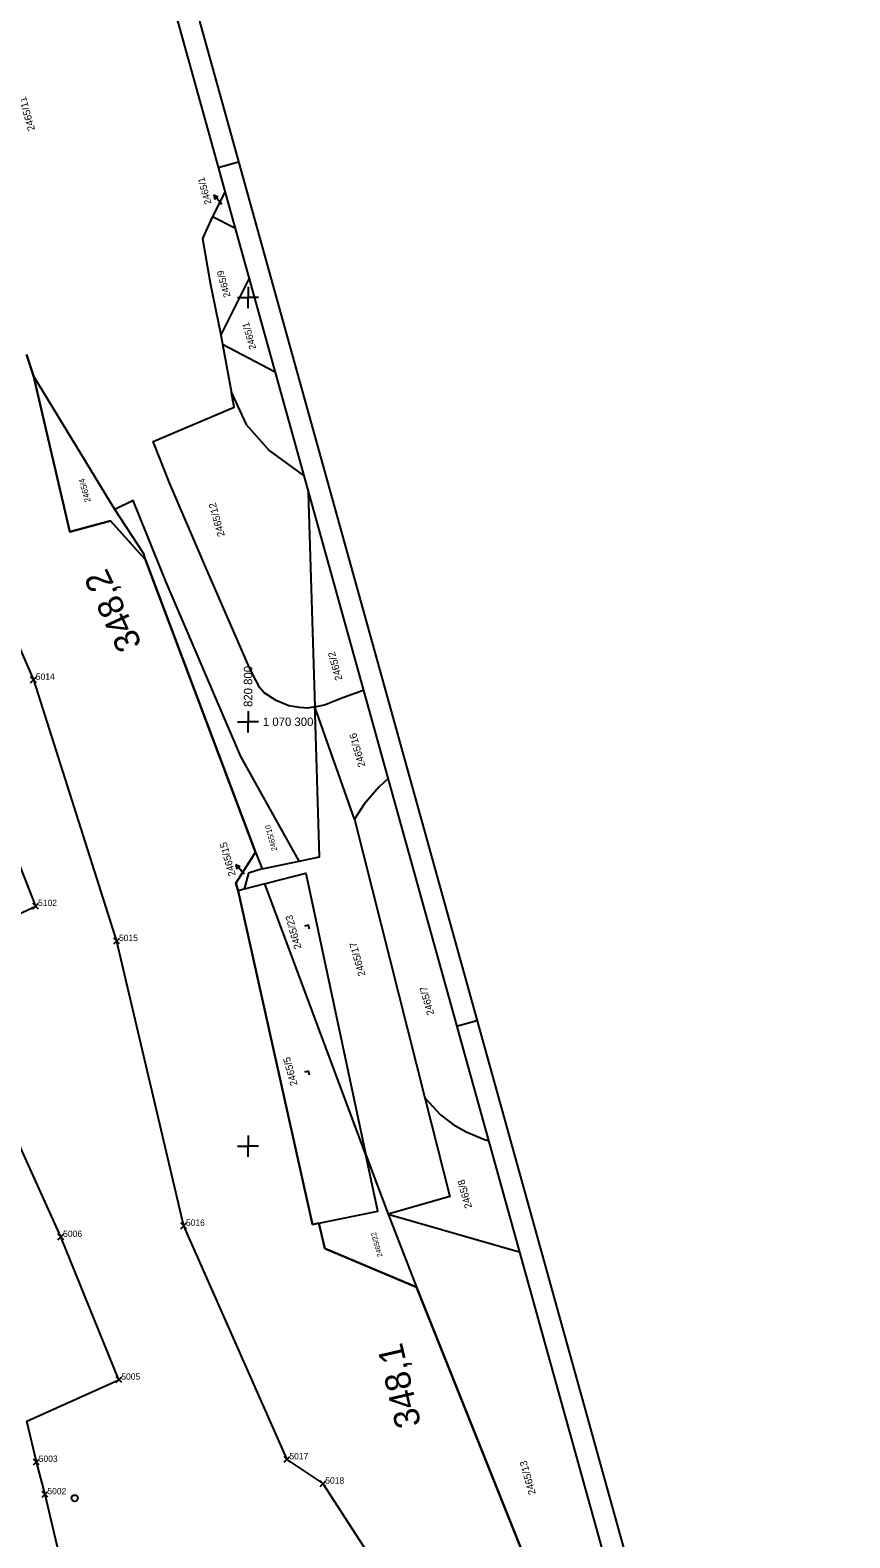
# Model space of a CAD drawing. Extents: x -821172 to -820632, y -1070921 to -1069931.
# Drawn here: x -820825.7 to -820729.1, y -1070396.2 to -1070218.5 of the extents above; entities that cross this region are included whole.
import ezdxf

# ---------------------------------------------------------------- set-up
doc = ezdxf.new("R2010")
doc.units = 0
for name, color, linetype in [('Ram', 7, 'Continuous'), ('Sit', 7, 'Continuous'), ('Sttaniceni a namezniky', 7, 'Continuous'), ('VB_bod_DZ', 7, 'Continuous'), ('Vrstva 52', 7, 'Continuous'), ('Vrstva 53', 7, 'Continuous'), ('Vrstva 55', 7, 'Continuous'), ('Vrstva 57', 7, 'Continuous'), ('Vrstva 59', 7, 'Continuous')]:
    doc.layers.add(name, color=color, linetype=linetype)

msp = doc.modelspace()

# ---------------------------------------------------------------- linework, layer by layer
at = {"layer": 'Ram'}
for p, q in [((-820801.13, -1070234.05), (-820803.54, -1070234.72)), ((-820773.02, -1070335.22), (-820775.42, -1070335.89))]:
    msp.add_line(p, q, dxfattribs=at)
for points in [[(-820857.35, -1070031.72), (-820632.46, -1070841.06)], [(-820859.09, -1070034.8), (-820635.54, -1070839.32), (-820916.88, -1070917.49)]]:
    msp.add_lwpolyline(points, dxfattribs=at)
at = {"layer": 'Sit'}
for p, q in [((-820800, -1070248.75), (-820800, -1070250)), ((-820800, -1070248.75), (-820800, -1070250)), ((-820801.25, -1070250), (-820800, -1070250)), ((-820801.25, -1070250), (-820800, -1070250)), ((-820798.75, -1070250), (-820800, -1070250)), ((-820800, -1070251.25), (-820800, -1070250)), ((-820800, -1070251.25), (-820800, -1070250)), ((-820798.75, -1070250), (-820800, -1070250)), ((-820801.25, -1070300), (-820800, -1070300)), ((-820800, -1070298.75), (-820800, -1070300)), ((-820798.75, -1070300), (-820800, -1070300)), ((-820800, -1070301.25), (-820800, -1070300)), ((-820801.25, -1070350), (-820800, -1070350)), ((-820800, -1070348.75), (-820800, -1070350)), ((-820798.75, -1070350), (-820800, -1070350)), ((-820800, -1070351.25), (-820800, -1070350))]:
    msp.add_line(p, q, dxfattribs=at)
at = {"layer": 'Sttaniceni a namezniky'}
msp.add_circle((-820820.44, -1070391.49), 0.375, dxfattribs=at)
at = {"layer": 'VB_bod_DZ'}
for p, q in [((-820825.63, -1070295.4), (-820824.95, -1070294.71)), ((-820824.95, -1070295.4), (-820825.63, -1070294.71)), ((-820825.37, -1070322.06), (-820824.69, -1070321.37)), ((-820824.69, -1070322.06), (-820825.37, -1070321.37)), ((-820815.83, -1070326.18), (-820815.15, -1070325.49)), ((-820815.15, -1070326.18), (-820815.83, -1070325.49)), ((-820822.41, -1070361.04), (-820821.72, -1070360.35)), ((-820821.72, -1070361.04), (-820822.41, -1070360.35)), ((-820807.94, -1070359.74), (-820807.25, -1070359.05)), ((-820807.25, -1070359.74), (-820807.94, -1070359.05)), ((-820815.56, -1070377.87), (-820814.87, -1070377.18)), ((-820814.87, -1070377.87), (-820815.56, -1070377.18)), ((-820825.29, -1070387.56), (-820824.6, -1070386.87)), ((-820824.6, -1070387.56), (-820825.29, -1070386.87)), ((-820795.76, -1070387.25), (-820795.07, -1070386.56)), ((-820795.07, -1070387.25), (-820795.76, -1070386.56)), ((-820824.27, -1070391.37), (-820823.58, -1070390.69)), ((-820823.58, -1070391.37), (-820824.27, -1070390.69)), ((-820791.52, -1070390.12), (-820790.83, -1070389.43)), ((-820790.83, -1070390.12), (-820791.52, -1070389.43))]:
    msp.add_line(p, q, dxfattribs=at)
at = {"layer": 'Vrstva 52'}
msp.add_lwpolyline([(-820782.06, -1070569.19), (-820823.93, -1070391.03), (-820824.95, -1070387.21), (-820826.08, -1070382.39), (-820815.22, -1070377.53), (-820822.07, -1070360.7), (-820836.66, -1070328.48), (-820839.3, -1070322.5), (-820846.11, -1070309.46), (-820851.46, -1070300.37), (-820856.81, -1070291.29), (-820843.48, -1070284.13), (-820833.99, -1070279.04), (-820832.86, -1070278.43), (-820830.46, -1070283.22), (-820825.29, -1070295.05), (-820815.49, -1070325.84), (-820807.6, -1070359.39), (-820795.41, -1070386.91), (-820791.18, -1070389.77), (-820780.82, -1070405.78)], dxfattribs=at)
msp.add_lwpolyline([(-820839.58, -1070284.56), (-820853.94, -1070291.42), (-820836.24, -1070326.89), (-820825.03, -1070321.71)], close=True, dxfattribs=at)
at = {"layer": 'Vrstva 53'}
for p, q in [((-820826.1, -1070256.7), (-820825.3, -1070259.25)), ((-820812.1, -1070280.9), (-820799.14, -1070315.36)), ((-820801.15, -1070319.91), (-820792.39, -1070359.23)), ((-820792.39, -1070359.23), (-820791.67, -1070359.08)), ((-820780.16, -1070366.62), (-820765.05, -1070404.29))]:
    msp.add_line(p, q, dxfattribs=at)
for points in [[(-820825.3, -1070259.25), (-820821, -1070277.6), (-820816.2, -1070276.3), (-820812.1, -1070280.9)], [(-820799.14, -1070315.36), (-820801.45, -1070319), (-820801.15, -1070319.91)], [(-820791.67, -1070359.08), (-820790.95, -1070362.05), (-820780.16, -1070366.62)]]:
    msp.add_lwpolyline(points, dxfattribs=at)
at = {"layer": 'Vrstva 55'}
for p, q in [((-820802.74, -1070237.6), (-820804.2, -1070240.46)), ((-820803.2, -1070254.4), (-820803, -1070255.5)), ((-820803, -1070255.5), (-820801.94, -1070261.25)), ((-820825.3, -1070259.25), (-820826.1, -1070256.7)), ((-820815.71, -1070274.99), (-820825.3, -1070259.25)), ((-820799.14, -1070315.36), (-820812.1, -1070280.9)), ((-820787.47, -1070311.48), (-820792.13, -1070298.22)), ((-820787.47, -1070311.48), (-820779.15, -1070344.32)), ((-820799.14, -1070315.36), (-820798.35, -1070317.32)), ((-820798.35, -1070317.32), (-820793.99, -1070316.42)), ((-820800.46, -1070319.73), (-820801.15, -1070319.91)), ((-820798.04, -1070319.1), (-820800.46, -1070319.73)), ((-820786.11, -1070351.02), (-820798.04, -1070319.1)), ((-820792.39, -1070359.23), (-820801.15, -1070319.91)), ((-820786.11, -1070351.02), (-820783.5, -1070358)), ((-820783.5, -1070358), (-820768.05, -1070362.44)), ((-820783.5, -1070358), (-820780.16, -1070366.62)), ((-820791.67, -1070359.08), (-820792.39, -1070359.23)), ((-820765.05, -1070404.29), (-820780.16, -1070366.62))]:
    msp.add_line(p, q, dxfattribs=at)
for points in [[(-820804.2, -1070240.46), (-820805.38, -1070243.04), (-820804.45, -1070248.28), (-820803.2, -1070254.4)], [(-820804.2, -1070240.46), (-820801.57, -1070241.78)], [(-820799.9, -1070247.81), (-820803.2, -1070254.4)], [(-820803, -1070255.5), (-820796.87, -1070258.72)], [(-820812.1, -1070280.9), (-820816.2, -1070276.3), (-820821, -1070277.6), (-820825.3, -1070259.25)], [(-820792.13, -1070298.22), (-820793, -1070298.4), (-820793.95, -1070298.3), (-820795.2, -1070298.1), (-820796.7, -1070297.5), (-820798.1, -1070296.6), (-820798.6, -1070296), (-820799.1, -1070295.1), (-820799.82, -1070293.66), (-820804.97, -1070281.8), (-820809.25, -1070271.85), (-820811.2, -1070266.98), (-820801.63, -1070262.92), (-820801.94, -1070261.25)], [(-820801.94, -1070261.25), (-820800.23, -1070264.95), (-820797.52, -1070268.04), (-820793.46, -1070270.97)], [(-820792.91, -1070272.96), (-820792.13, -1070298.22)], [(-820793.99, -1070316.42), (-820800.87, -1070304.08), (-820809.66, -1070283.54), (-820813.53, -1070273.91), (-820815.71, -1070274.99)], [(-820812.1, -1070280.9), (-820812.3, -1070280.2), (-820815.71, -1070274.99)], [(-820792.13, -1070298.22), (-820791, -1070298), (-820788.84, -1070297.13), (-820786.43, -1070296.28)], [(-820793.99, -1070316.42), (-820791.57, -1070315.92), (-820792.1, -1070299.04), (-820792.13, -1070298.22)], [(-820783.53, -1070306.73), (-820784.56, -1070307.68), (-820786.32, -1070309.72), (-820787.47, -1070311.48)], [(-820801.15, -1070319.91), (-820801.45, -1070319), (-820799.14, -1070315.36)], [(-820798.35, -1070317.32), (-820799.93, -1070317.83), (-820800.46, -1070319.73)], [(-820798.04, -1070319.1), (-820797.62, -1070318.99), (-820793.2, -1070317.84), (-820786.11, -1070351.02)], [(-820779.15, -1070344.32), (-820776.21, -1070355.93), (-820783.5, -1070358)], [(-820779.15, -1070344.32), (-820777.33, -1070346.31), (-820775.83, -1070347.45), (-820774.3, -1070348.31), (-820772.13, -1070349.23), (-820771.69, -1070349.33)], [(-820791.67, -1070359.08), (-820784.69, -1070357.66), (-820786.11, -1070351.02)], [(-820780.16, -1070366.62), (-820790.95, -1070362.05), (-820791.67, -1070359.08)]]:
    msp.add_lwpolyline(points, dxfattribs=at)
at = {"layer": 'Vrstva 57'}
for p, q in [((-820803.08, -1070239.06), (-820804.05, -1070237.92)), ((-820804.05, -1070237.92), (-820803.53, -1070238.13)), ((-820804.05, -1070237.92), (-820803.92, -1070238.46)), ((-820800.47, -1070317.96), (-820801.44, -1070316.82)), ((-820801.44, -1070316.82), (-820800.93, -1070317.04)), ((-820801.44, -1070316.82), (-820801.31, -1070317.36))]:
    msp.add_line(p, q, dxfattribs=at)
at = {"layer": 'Vrstva 59'}
for p, q in [((-820792.87, -1070323.96), (-820793.35, -1070324.08)), ((-820792.74, -1070324.44), (-820792.87, -1070323.96)), ((-820792.87, -1070341.16), (-820793.35, -1070341.29)), ((-820792.74, -1070341.65), (-820792.87, -1070341.16))]:
    msp.add_line(p, q, dxfattribs=at)

# ---------------------------------------------------------------- texts
at = {"layer": 'Sit'}
msp.add_text('820 800', height=1, rotation=90, dxfattribs=at).set_placement((-820799.5, -1070298.25))
msp.add_text('1 070 300', height=1, dxfattribs=at).set_placement((-820798.25, -1070300.5))
at = {"layer": 'Sttaniceni a namezniky'}
for s, rotation, p in [('348,2', 114.979, (-820812.46, -1070290.87)), ('348,1', 103.1701, (-820779.59, -1070382.81))]:
    msp.add_text(s, height=3, rotation=rotation, dxfattribs=at).set_placement(p)
at = {"layer": 'VB_bod_DZ'}
for s, p in [(' 5014', (-820825.29, -1070295.05)), (' 5102', (-820825.03, -1070321.71)), (' 5015', (-820815.49, -1070325.84)), (' 5016', (-820807.6, -1070359.39)), (' 5006', (-820822.07, -1070360.7)), (' 5005', (-820815.22, -1070377.53)), (' 5003', (-820824.95, -1070387.21)), (' 5017', (-820795.41, -1070386.91)), (' 5018', (-820791.18, -1070389.77)), (' 5002', (-820823.93, -1070391.03))]:
    msp.add_text(s, height=0.75, dxfattribs=at).set_placement(p)
at = {"layer": 'Vrstva 57'}
for s, height, p in [('2465/11', 0.85, (-820825.09, -1070230.24)), ('2465/1', 0.8, (-820804.3, -1070238.91)), ('2465/9', 0.8, (-820802.05, -1070249.88)), ('2465/1', 0.8, (-820799.04, -1070256.01)), ('2465/4', 0.7, (-820818.53, -1070274.02)), ('2465/12', 0.85, (-820802.73, -1070278.06)), ('2465/2', 0.85, (-820788.86, -1070295.01)), ('2465/16', 0.85, (-820786.17, -1070305.21)), ('2465/10', 0.65, (-820796.55, -1070315.13)), ('2465/15', 0.85, (-820801.44, -1070318.07)), ('2465/23', 0.85, (-820793.7, -1070326.65)), ('2465/17', 0.85, (-820786.15, -1070329.85)), ('2465/7', 0.85, (-820778.05, -1070334.44)), ('2465/5', 0.85, (-820794.15, -1070342.77)), ('2465/8', 0.85, (-820773.59, -1070357.21)), ('2465/22', 0.6, (-820784.14, -1070362.98)), ('2465/13', 0.85, (-820766.08, -1070390.95))]:
    msp.add_text(s, height=height, rotation=105.5289, dxfattribs=at).set_placement(p)

doc.saveas('drawing.dxf')
